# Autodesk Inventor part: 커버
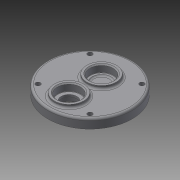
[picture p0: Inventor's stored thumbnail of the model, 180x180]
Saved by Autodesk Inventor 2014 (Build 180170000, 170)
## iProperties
Created: 2015-07
Part Number: 커버
Material: Generic
Document SubType Name: Modeling
Designer: Administrator
Density: 1 g/cm^3
Appearance: Default
Author: Administrator
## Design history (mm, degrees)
sketch "스케치1"
  geometry: C1 r 40 at (0, 0); 1 further point
  constraints: 1 centre point, 1 coincident
  dimensions: "d0" = 80 diameter of C1
extrude "돌출1" new body sketch "스케치1" distance "d1" = 9; taper "d2" = 0 deg
sketch "스케치2"
  geometry: C1 r 40 at (0, 0) reference; C2 r 14 at (0, 11); C3 r 14 at (0, -20)
  constraints: 2 centre point, 2 vertical alignment
  dimensions: "d3" = 28 diameter of C3; "d4" = 20 distance of C3.centre C1.centre; "d5" = 11 distance of C2.centre C1.centre; "d6" = 28 diameter of C2
extrude "돌출2" join sketch "스케치2" distance "d7" = 3; taper "d8" = 0 deg
sketch "스케치3"
  geometry: C1 r 14 at (0, 0) reference; C2 r 11 at (0, 0); 1 further point
  constraints: 1 centre point, 1 coincident
  dimensions: "d9" = 22 diameter of C2
extrude "돌출3" cut sketch "스케치3" distance "d10" = 7; taper "d11" = 0 deg
sketch "스케치4"
  geometry: C1 r 9 at (0, 0); 2 further points
  constraints: 1 centre point, 1 coincident, 1 vertical alignment
  dimensions: "d12" = 18 diameter of C1
extrude "돌출4" cut sketch "스케치4" distance "d13" = 1; taper "d14" = 0 deg
sketch "스케치5"
  geometry: C1 r 14 at (0, 0) reference; C2 r 11 at (0, 0); 1 further point
  constraints: 1 centre point, 1 coincident
  dimensions: "d15" = 22 diameter of C2
extrude "돌출5" cut sketch "스케치5" distance "d16" = 7; taper "d17" = 0 deg
sketch "스케치6"
  geometry: C1 r 11 at (0, 0) reference; C2 r 7.5 at (0, 0); 1 further point
  constraints: 1 centre point, 1 coincident
  dimensions: "d18" = 15 diameter of C2
extrude "돌출6" cut sketch "스케치6" distance "d19" = 2; taper "d20" = 0 deg
sketch "스케치7"
  geometry: C1 r 40 at (0, 0) reference; C2 r 15 at (0, -20)
  constraints: 1 centre point, 1 vertical alignment
  dimensions: "d21" = 20 distance of C2.centre C1.centre; "d22" = 30 diameter of C2
extrude "돌출7" join sketch "스케치7" distance "d23" = 4; taper "d24" = 0 deg
sketch "스케치8"
  geometry: C1 r 15 at (0, 0) reference; C2 r 11 at (0, 0); 1 further point
  constraints: 1 centre point, 1 coincident
  dimensions: "d25" = 22 diameter of C2
extrude "돌출8" cut sketch "스케치8" distance "d26" = 7; taper "d27" = 0 deg
sketch "스케치9" dims "d28" = 70
  geometry: L1 (0, 0)-(40, 0); L2 (0, 0)-(24.749, 24.749); C1 r 4 at (24.749, 24.749); 1 further point
  constraints: 4 end point, 2 coincident, 1 centre point, 1 horizontal, 1 horizontal alignment, 4 other
  dimensions: "d29" = 45 deg angle of L1 L2; "d30" = 8 diameter of C1
extrude "돌출9" cut sketch "스케치9" distance "d31" = 4.4; taper "d32" = 0 deg
sketch "스케치10"
  geometry: C1 r 4 at (0, 0) reference; C2 r 2.25 at (0, 0); 1 further point
  constraints: 1 centre point, 1 coincident
  dimensions: "d33" = 4.5 diameter of C2
extrude "돌출10" cut sketch "스케치10" stored distance "d34" = 4.4; taper "d35" = 0 deg
fillet "모깎기1" dims "d39" = 0.3
chamfer "모따기1" distance "d40" = 1; stored, may be unused: second distance "d41" = 2, angle "d42" = 45 deg
fillet "모깎기2" dims "d43" = 2
fillet "모깎기3" dims "d44" = 2
node "솔리드1"
pattern_circular "원형 패턴1" dims angle "d37" = 360 deg
